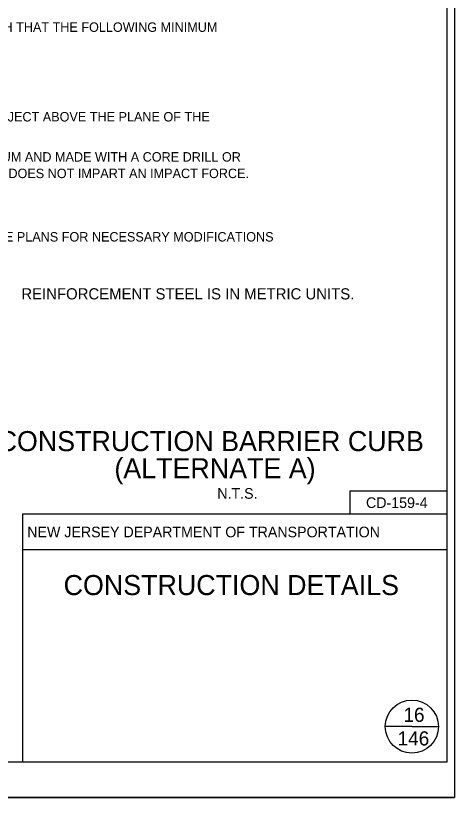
# Model space of a CAD drawing. Extents: x 499866 to 500993, y 499985 to 500645.
# Drawn here: x 500807.1 to 500993, y 499985 to 500316.4 of the extents above; entities that cross this region are included whole.
import ezdxf

# ---------------------------------------------------------------- set-up
doc = ezdxf.new("R2010")
doc.units = 0
for name, color, linetype in [('1', 7, 'Continuous'), ('41', 7, 'Continuous'), ('5', 7, 'Continuous'), ('63', 7, 'Continuous')]:
    doc.layers.add(name, color=color, linetype=linetype)

msp = doc.modelspace()

# ---------------------------------------------------------------- linework, layer by layer
at = {"layer": '1'}
for p, q in [((500990, 500000), (500990, 500630)), ((500990, 500114.84), (500948.66, 500114.84)), ((500948.66, 500114.84), (500948.66, 500105)), ((500990, 500105), (500810, 500105)), ((500810, 500105), (500810, 500000)), ((500990, 500090), (500810, 500090)), ((500975, 500015), (500963.75, 500015)), ((500975, 500015), (500986.25, 500015)), ((500000, 500000), (500990, 500000)), ((499944.83, 499985), (500993, 499985))]:
    msp.add_line(p, q, dxfattribs=at)
msp.add_circle((500975, 500015), 11.25, dxfattribs=at)
at = {"layer": '41'}
msp.add_line((500901, 500115.67), (500901, 500115.67), dxfattribs=at)
msp.add_lwpolyline([(499944.83, 500645), (500993, 500645), (500993, 499985), (499944.83, 499985)], close=True, dxfattribs=at)

# ---------------------------------------------------------------- texts
at = {"layer": '1'}
for s, height, p in [('REINFORCEMENT STEEL IS IN METRIC UNITS.', 4.7244, (500809.53, 500196.1)), ('CD-159-4', 4.5, (500955.57, 500107.67)), ('NEW JERSEY DEPARTMENT OF TRANSPORTATION', 4.5, (500812.02, 500095.25)), ('CONSTRUCTION DETAILS', 8.5, (500827.44, 500070.75)), ('146', 6, (500968.97, 500007))]:
    msp.add_text(s, height=height, dxfattribs=at).set_placement(p)
at = {"layer": '5'}
for s, height, p in [('ENSURE THAT THE LENGTH OF THE ANCHOR PIN IS SUCH THAT THE FOLLOWING MINIMUM ', 4, (500653.37, 500309.52)), ('WHEN ANCHOR PINS ARE IN PLACE, THEY WILL NOT PROJECT ABOVE THE PLANE OF THE', 4, (500653.37, 500271.52)), ('HOLES IN BRIDGE DECKS TO BE 1 1/4" DIAMETER MAXIMUM AND MADE WITH A CORE DRILL OR', 4, (500653.37, 500254.52)), ('ANY OTHER APPROVED ROTARY DRILLING DEVICE THAT DOES NOT IMPART AN IMPACT FORCE.', 4, (500653.37, 500247.52)), ('FOR INSTALLATION ON BRIDGE DECKS REFER TO BRIDGE PLANS FOR NECESSARY MODIFICATIONS', 4, (500653.37, 500220.64)), ('CONSTRUCTION BARRIER CURB', 8.5, (500799.47, 500131.77)), ('(ALTERNATE A)', 8.5, (500848.96, 500120.27)), ('N.T.S.', 4.5, (500892.56, 500111.6))]:
    msp.add_text(s, height=height, dxfattribs=at).set_placement(p)
at = {"layer": '63'}
msp.add_text('16', height=6, dxfattribs=at).set_placement((500971.43, 500017))

doc.saveas('drawing.dxf')
